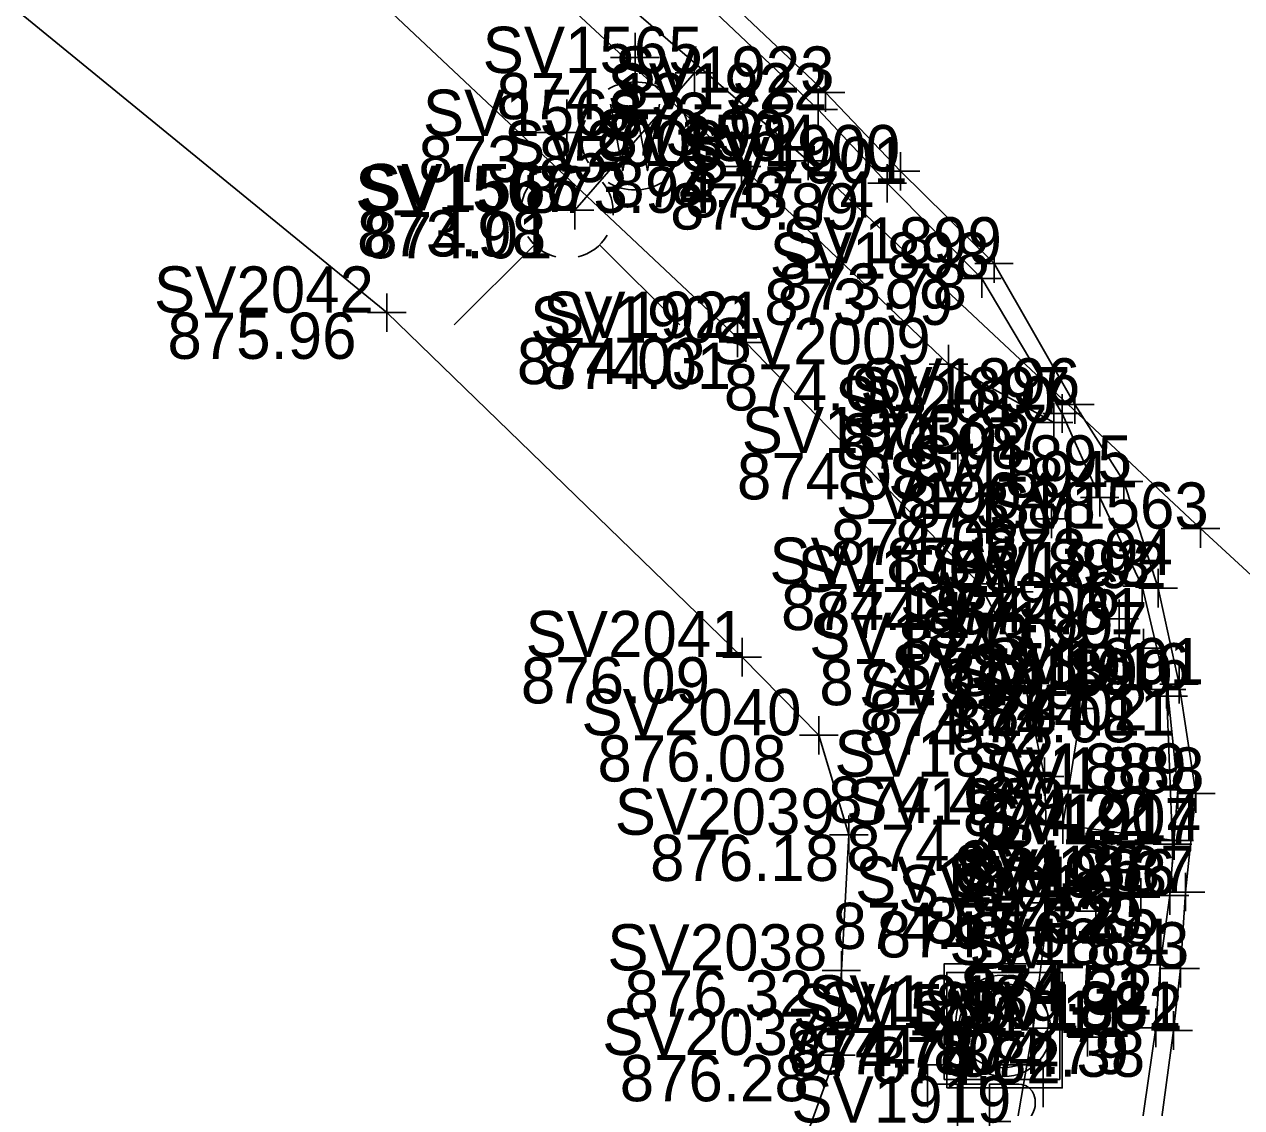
# Model space of a CAD drawing. Extents: x 1480001 to 1480402, y 379235 to 379603.
# Drawn here: x 1480114.39 to 1480145.99, y 379405.99 to 379434.1 of the extents above; entities that cross this region are included whole.
import ezdxf

# ---------------------------------------------------------------- set-up
doc = ezdxf.new("R2010")
doc.units = 0
for name, color, linetype in [('PV_X_Curb', 7, 'Continuous'), ('PV_X_Walk', 7, 'Continuous'), ('RD_X_Concrete_Pad', 7, 'Continuous'), ('SG_X_Poles', 7, 'Continuous'), ('SG_X_PullBox', 7, 'Continuous'), ('SV_X_Break_Lines', 7, 'Continuous'), ('SV_X_Shot_Marker', 7, 'Continuous'), ('SV_X_Text_Elevation', 7, 'Continuous'), ('SV_X_Text_Name', 7, 'Continuous'), ('UT_X_Water', 7, 'Continuous'), ('UT_X_Water_Cells', 7, 'Continuous')]:
    doc.layers.add(name, color=color, linetype=linetype)

msp = doc.modelspace()

# ---------------------------------------------------------------- linework, layer by layer
at = {"layer": 'PV_X_Curb'}
for points in [[(1480097.272, 379349.731), (1480114.906, 379368.678), (1480120.582, 379374.885), (1480122.682, 379377.153), (1480124.005, 379378.548), (1480138.475, 379394.29), (1480139.717, 379395.951), (1480141.648, 379398.861), (1480143.063, 379403.22), (1480143.762, 379408.065), (1480143.873, 379409.698), (1480144.124, 379411.499), (1480144.338, 379414.245), (1480144.085, 379416.674), (1480143.405, 379419.529), (1480142.307, 379421.83), (1480141.33, 379424.009), (1480139.247, 379427.506), (1480136.787, 379429.98), (1480135, 379431.897), (1480118.039, 379447.914)], [(1480097.622, 379349.287), (1480115.163, 379368.135), (1480120.989, 379374.507), (1480122.913, 379376.573), (1480123.248, 379376.579), (1480124.233, 379378.045), (1480138.666, 379393.676), (1480140.342, 379395.44), (1480142.173, 379398.797), (1480143.522, 379402.786), (1480144.219, 379407.995), (1480144.4, 379409.609), (1480144.536, 379411.589), (1480144.804, 379414.142), (1480144.365, 379416.981), (1480143.824, 379419.476), (1480142.93, 379422.24), (1480141.664, 379424.24), (1480139.564, 379427.9), (1480137.133, 379430.292), (1480135.19, 379432.332), (1480118.45, 379448.16)]]:
    msp.add_lwpolyline(points, dxfattribs=at)
at = {"layer": 'PV_X_Walk'}
for points in [[(1480106.316, 379456.227), (1480120.51, 379442.034), (1480133.01, 379430.413), (1480138.38, 379425.286), (1480141.112, 379423.774)], [(1480035.484, 379289.224), (1480050.568, 379305.437), (1480062.335, 379317.896), (1480064.038, 379319.719), (1480070.805, 379327.066), (1480078.054, 379334.946), (1480079.953, 379336.866), (1480094.208, 379352.393), (1480112.048, 379371.575), (1480117.348, 379377.211), (1480119.911, 379379.906), (1480121.511, 379381.77), (1480134.604, 379395.58), (1480136.695, 379398.148), (1480138.778, 379401.149), (1480140.004, 379404.725), (1480140.577, 379408.06), (1480140.982, 379411.311), (1480140.871, 379414.584), (1480140.225, 379417.636), (1480139.184, 379419.586), (1480133.124, 379425.845), (1480132.903, 379425.968), (1480114.834, 379442.96)]]:
    msp.add_lwpolyline(points, dxfattribs=at)
at = {"layer": 'RD_X_Concrete_Pad'}
msp.add_lwpolyline([(1480144.243, 379412.927), (1480141.349, 379413.336), (1480141.909, 379416.834), (1480144.038, 379416.848), (1480144.194, 379412.83)], dxfattribs=at)
at = {"layer": 'SG_X_Poles'}
for points in [[(1480138.271, 379406.729), (1480141.271, 379406.729), (1480141.271, 379409.729), (1480138.271, 379409.729)], [(1480138.334, 379406.505), (1480141.334, 379406.505), (1480141.334, 379409.505), (1480138.334, 379409.505)]]:
    msp.add_lwpolyline(points, close=True, dxfattribs=at)
for centre in [(1480139.771, 379408.229), (1480139.834, 379408.005)]:
    msp.add_circle(centre, 1.2, dxfattribs=at)
at = {"layer": 'SG_X_PullBox'}
for points in [[(1480138.937, 379407.108), (1480137.837, 379407.108), (1480137.837, 379406.008)], [(1480140.837, 379406.008), (1480140.837, 379407.108), (1480139.737, 379407.108)], [(1480137.981, 379406.608), (1480139.225, 379406.608)], [(1480138.611, 379406.608), (1480138.611, 379404.608)], [(1480139.449, 379404.608), (1480139.449, 379406.608), (1480140.205, 379406.608), (1480140.283, 379406.592), (1480140.394, 379406.56), (1480140.441, 379406.529), (1480140.488, 379406.497), (1480140.551, 379406.419), (1480140.598, 379406.34), (1480140.63, 379406.214), (1480140.63, 379406.025), (1480140.614, 379405.962), (1480140.583, 379405.868), (1480140.52, 379405.757), (1480140.457, 379405.71), (1480140.409, 379405.679), (1480140.378, 379405.663), (1480140.331, 379405.647), (1480140.189, 379405.631), (1480139.449, 379405.631)]]:
    msp.add_lwpolyline(points, dxfattribs=at)
at = {"layer": 'SV_X_Break_Lines'}
msp.add_lwpolyline([(1480127.721, 379395.358), (1480131.799, 379398.039), (1480133.273, 379401.352), (1480135.459, 379407.36), (1480135.6, 379409.555), (1480135.793, 379413.076), (1480135.014, 379415.657), (1480133.026, 379417.684), (1480123.803, 379426.624), (1480113.121, 379435.343), (1480106.984, 379440.926), (1480103.73, 379443.918), (1480102.529, 379445.074), (1480100.774, 379445.951), (1480096.595, 379444.059), (1480092.174, 379441.029), (1480086.377, 379436.591)], dxfattribs=at)
at = {"layer": 'SV_X_Shot_Marker'}
for p, q in [((1480131.786, 379433.343), (1480131.786, 379432.343)), ((1480131.286, 379432.843), (1480132.286, 379432.843)), ((1480131.786, 379432.843), (1480131.786, 379432.843)), ((1480135.19, 379432.832), (1480135.19, 379431.832)), ((1480134.69, 379432.332), (1480135.69, 379432.332)), ((1480135, 379432.397), (1480135, 379431.397)), ((1480135.19, 379432.332), (1480135.19, 379432.332)), ((1480134.5, 379431.897), (1480135.5, 379431.897)), ((1480135, 379431.897), (1480135, 379431.897)), ((1480133.01, 379430.913), (1480133.01, 379429.913)), ((1480134.739, 379431.059), (1480134.739, 379430.059)), ((1480134.239, 379430.559), (1480135.239, 379430.559)), ((1480134.739, 379430.559), (1480134.739, 379430.559)), ((1480137.133, 379430.792), (1480137.133, 379429.792)), ((1480132.51, 379430.413), (1480133.51, 379430.413)), ((1480133.01, 379430.413), (1480133.01, 379430.413)), ((1480136.633, 379430.292), (1480137.633, 379430.292)), ((1480136.787, 379430.48), (1480136.787, 379429.48)), ((1480137.133, 379430.292), (1480137.133, 379430.292)), ((1480136.287, 379429.98), (1480137.287, 379429.98)), ((1480136.787, 379429.98), (1480136.787, 379429.98)), ((1480128.679, 379429.782), (1480128.679, 379428.782)), ((1480128.179, 379429.282), (1480129.179, 379429.282)), ((1480128.679, 379429.282), (1480128.679, 379429.282)), ((1480139.564, 379428.4), (1480139.564, 379427.4)), ((1480139.247, 379428.006), (1480139.247, 379427.006)), ((1480139.064, 379427.9), (1480140.064, 379427.9)), ((1480139.564, 379427.9), (1480139.564, 379427.9)), ((1480138.747, 379427.506), (1480139.747, 379427.506)), ((1480139.247, 379427.506), (1480139.247, 379427.506)), ((1480123.803, 379427.124), (1480123.803, 379426.124)), ((1480123.303, 379426.624), (1480124.303, 379426.624)), ((1480123.803, 379426.624), (1480123.803, 379426.624)), ((1480132.903, 379426.468), (1480132.903, 379425.468)), ((1480133.124, 379426.345), (1480133.124, 379425.345)), ((1480132.403, 379425.968), (1480133.403, 379425.968)), ((1480132.624, 379425.845), (1480133.624, 379425.845)), ((1480132.903, 379425.968), (1480132.903, 379425.968)), ((1480133.124, 379425.845), (1480133.124, 379425.845)), ((1480138.38, 379425.786), (1480138.38, 379424.786)), ((1480137.88, 379425.286), (1480138.88, 379425.286)), ((1480138.38, 379425.286), (1480138.38, 379425.286)), ((1480141.33, 379424.509), (1480141.33, 379423.509)), ((1480141.664, 379424.74), (1480141.664, 379423.74)), ((1480141.112, 379424.274), (1480141.112, 379423.274)), ((1480141.164, 379424.24), (1480142.164, 379424.24)), ((1480141.664, 379424.24), (1480141.664, 379424.24)), ((1480140.83, 379424.009), (1480141.83, 379424.009)), ((1480141.33, 379424.009), (1480141.33, 379424.009)), ((1480140.612, 379423.774), (1480141.612, 379423.774)), ((1480141.112, 379423.774), (1480141.112, 379423.774)), ((1480138.625, 379423.478), (1480138.625, 379422.478)), ((1480138.125, 379422.978), (1480139.125, 379422.978)), ((1480138.625, 379422.978), (1480138.625, 379422.978)), ((1480142.93, 379422.74), (1480142.93, 379421.74)), ((1480142.307, 379422.33), (1480142.307, 379421.33)), ((1480142.43, 379422.24), (1480143.43, 379422.24)), ((1480142.93, 379422.24), (1480142.93, 379422.24)), ((1480141.058, 379421.773), (1480141.058, 379420.773)), ((1480141.807, 379421.83), (1480142.807, 379421.83)), ((1480142.307, 379421.83), (1480142.307, 379421.83)), ((1480144.924, 379421.519), (1480144.924, 379420.519)), ((1480140.558, 379421.273), (1480141.558, 379421.273)), ((1480141.058, 379421.273), (1480141.058, 379421.273)), ((1480144.424, 379421.019), (1480145.424, 379421.019)), ((1480144.924, 379421.019), (1480144.924, 379421.019)), ((1480139.184, 379420.086), (1480139.184, 379419.086)), ((1480140.079, 379419.878), (1480140.079, 379418.878)), ((1480143.405, 379420.029), (1480143.405, 379419.029)), ((1480143.824, 379419.976), (1480143.824, 379418.976)), ((1480138.684, 379419.586), (1480139.684, 379419.586)), ((1480139.184, 379419.586), (1480139.184, 379419.586)), ((1480142.905, 379419.529), (1480143.905, 379419.529)), ((1480143.324, 379419.476), (1480144.324, 379419.476)), ((1480143.405, 379419.529), (1480143.405, 379419.529)), ((1480143.824, 379419.476), (1480143.824, 379419.476)), ((1480139.579, 379419.378), (1480140.579, 379419.378)), ((1480140.079, 379419.378), (1480140.079, 379419.378)), ((1480142.812, 379419.182), (1480142.812, 379418.182)), ((1480142.312, 379418.682), (1480143.312, 379418.682)), ((1480142.812, 379418.682), (1480142.812, 379418.682)), ((1480143.444, 379418.417), (1480143.444, 379417.417)), ((1480133.026, 379418.184), (1480133.026, 379417.184)), ((1480140.225, 379418.136), (1480140.225, 379417.136)), ((1480142.944, 379417.917), (1480143.944, 379417.917)), ((1480143.444, 379417.917), (1480143.444, 379417.917)), ((1480132.526, 379417.684), (1480133.526, 379417.684)), ((1480133.026, 379417.684), (1480133.026, 379417.684)), ((1480139.725, 379417.636), (1480140.725, 379417.636)), ((1480140.225, 379417.636), (1480140.225, 379417.636)), ((1480141.909, 379417.334), (1480141.909, 379416.334)), ((1480144.038, 379417.348), (1480144.038, 379416.348)), ((1480144.365, 379417.481), (1480144.365, 379416.481)), ((1480143.865, 379416.981), (1480144.865, 379416.981)), ((1480144.085, 379417.174), (1480144.085, 379416.174)), ((1480144.365, 379416.981), (1480144.365, 379416.981)), ((1480141.409, 379416.834), (1480142.409, 379416.834)), ((1480141.679, 379416.851), (1480141.679, 379415.851)), ((1480141.909, 379416.834), (1480141.909, 379416.834)), ((1480143.538, 379416.848), (1480144.538, 379416.848)), ((1480143.585, 379416.674), (1480144.585, 379416.674)), ((1480144.038, 379416.848), (1480144.038, 379416.848)), ((1480144.085, 379416.674), (1480144.085, 379416.674)), ((1480141.179, 379416.351), (1480142.179, 379416.351)), ((1480141.679, 379416.351), (1480141.679, 379416.351)), ((1480135.014, 379416.157), (1480135.014, 379415.157)), ((1480134.514, 379415.657), (1480135.514, 379415.657)), ((1480135.014, 379415.657), (1480135.014, 379415.657)), ((1480140.871, 379415.084), (1480140.871, 379414.084)), ((1480144.338, 379414.745), (1480144.338, 379413.745)), ((1480140.371, 379414.584), (1480141.371, 379414.584)), ((1480140.871, 379414.584), (1480140.871, 379414.584)), ((1480144.804, 379414.642), (1480144.804, 379413.642)), ((1480143.838, 379414.245), (1480144.838, 379414.245)), ((1480144.304, 379414.142), (1480145.304, 379414.142)), ((1480144.338, 379414.245), (1480144.338, 379414.245)), ((1480144.804, 379414.142), (1480144.804, 379414.142)), ((1480141.349, 379413.836), (1480141.349, 379412.836)), ((1480135.793, 379413.576), (1480135.793, 379412.576)), ((1480140.849, 379413.336), (1480141.849, 379413.336)), ((1480141.349, 379413.336), (1480141.349, 379413.336)), ((1480144.194, 379413.33), (1480144.194, 379412.33)), ((1480144.243, 379413.427), (1480144.243, 379412.427)), ((1480135.293, 379413.076), (1480136.293, 379413.076)), ((1480135.793, 379413.076), (1480135.793, 379413.076)), ((1480143.694, 379412.83), (1480144.694, 379412.83)), ((1480143.743, 379412.927), (1480144.743, 379412.927)), ((1480144.194, 379412.83), (1480144.194, 379412.83)), ((1480144.243, 379412.927), (1480144.243, 379412.927)), ((1480143.37, 379411.952), (1480143.37, 379410.952)), ((1480144.124, 379411.999), (1480144.124, 379410.999)), ((1480144.536, 379412.089), (1480144.536, 379411.089)), ((1480140.982, 379411.811), (1480140.982, 379410.811)), ((1480142.207, 379411.592), (1480142.207, 379410.592)), ((1480144.036, 379411.589), (1480145.036, 379411.589)), ((1480144.536, 379411.589), (1480144.536, 379411.589)), ((1480140.482, 379411.311), (1480141.482, 379411.311)), ((1480140.982, 379411.311), (1480140.982, 379411.311)), ((1480142.87, 379411.452), (1480143.87, 379411.452)), ((1480143.37, 379411.452), (1480143.37, 379411.452)), ((1480143.624, 379411.499), (1480144.624, 379411.499)), ((1480144.124, 379411.499), (1480144.124, 379411.499)), ((1480141.707, 379411.092), (1480142.707, 379411.092)), ((1480142.207, 379411.092), (1480142.207, 379411.092)), ((1480135.6, 379410.055), (1480135.6, 379409.055)), ((1480143.873, 379410.198), (1480143.873, 379409.198)), ((1480144.4, 379410.109), (1480144.4, 379409.109)), ((1480143.373, 379409.698), (1480144.373, 379409.698)), ((1480143.873, 379409.698), (1480143.873, 379409.698)), ((1480135.1, 379409.555), (1480136.1, 379409.555)), ((1480135.6, 379409.555), (1480135.6, 379409.555)), ((1480143.9, 379409.609), (1480144.9, 379409.609)), ((1480144.4, 379409.609), (1480144.4, 379409.609)), ((1480140.577, 379408.56), (1480140.577, 379407.56)), ((1480143.762, 379408.565), (1480143.762, 379407.565)), ((1480144.219, 379408.495), (1480144.219, 379407.495)), ((1480141.99, 379408.326), (1480141.99, 379407.326)), ((1480135.459, 379407.86), (1480135.459, 379406.86)), ((1480140.077, 379408.06), (1480141.077, 379408.06)), ((1480140.577, 379408.06), (1480140.577, 379408.06)), ((1480141.49, 379407.826), (1480142.49, 379407.826)), ((1480141.99, 379407.826), (1480141.99, 379407.826)), ((1480143.262, 379408.065), (1480144.262, 379408.065)), ((1480143.719, 379407.995), (1480144.719, 379407.995)), ((1480143.762, 379408.065), (1480143.762, 379408.065)), ((1480144.219, 379407.995), (1480144.219, 379407.995)), ((1480134.959, 379407.36), (1480135.959, 379407.36)), ((1480135.459, 379407.36), (1480135.459, 379407.36))]:
    msp.add_line(p, q, dxfattribs=at)
at = {"layer": 'UT_X_Water'}
msp.add_line((1480131.786, 379432.843), (1480128.679, 379429.282), dxfattribs=at)
msp.add_lwpolyline([(1480225.088, 379345.601), (1480208.322, 379361.342), (1480207.346, 379362.25), (1480199.528, 379369.768), (1480193.21, 379375.651), (1480182.823, 379385.139), (1480177.927, 379389.525), (1480169.423, 379398.321), (1480161.035, 379406.189), (1480144.924, 379421.019), (1480134.739, 379430.559), (1480121.485, 379441.998), (1480113.085, 379450.369), (1480106.418, 379456.915), (1480094.539, 379467.985), (1480089.15, 379472.551), (1480086.751, 379474.713), (1480073.459, 379487.337), (1480068.123, 379493.187), (1480050.678, 379510.207), (1480044.404, 379515.873)], dxfattribs=at)
at = {"layer": 'UT_X_Water_Cells'}
for p, q in [((1480130.245, 379432.61), (1480130.245, 379433.881)), ((1480130.88, 379433.246), (1480129.608, 379433.246)), ((1480128.478, 379430.438), (1480128.478, 379432.158)), ((1480129.678, 379431.298), (1480127.278, 379431.298)), ((1480130.245, 379431.21), (1480130.245, 379431.21)), ((1480128.48, 379429.234), (1480128.48, 379429.234)), ((1480128.48, 379429.234), (1480128.48, 379429.234)), ((1480127.633, 379428.386), (1480125.553, 379426.308)), ((1480129.325, 379428.386), (1480131.405, 379426.308))]:
    msp.add_line(p, q, dxfattribs=at)
msp.add_lwpolyline([(1480129.608, 379432.03), (1480129.927, 379430.306), (1480130.245, 379432.03), (1480130.565, 379430.306), (1480130.882, 379432.03)], dxfattribs=at)
for centre, radius, start, end in [((1480130.245, 379431.211), 1.4, 60.0184, 120.0157), ((1480130.245, 379431.211), 1.4, 150.0184, 209.9816), ((1480130.245, 379431.211), 1.4, 330.0184, 29.9816), ((1480128.48, 379429.234), 1.2, 68.1395, 112.038), ((1480128.48, 379429.234), 1.2, 140.021, 184.0629), ((1480128.48, 379429.234), 1.2, 356.0165, 39.9889), ((1480130.245, 379431.211), 1.4, 239.9843, 299.9816), ((1480128.48, 379429.234), 1.2, 283.8239, 329.9097), ((1480128.48, 379429.234), 1.2, 211.8788, 255.8479)]:
    msp.add_arc(centre, radius, start, end, dxfattribs=at)

# ---------------------------------------------------------------- texts
at = {"layer": 'SV_X_Text_Elevation'}
for s, p in [('874.13', (1480126.647, 379431.643)), ('873.68', (1480129.54, 379431.132)), ('873.90', (1480129.255, 379430.697)), ('873.85', (1480124.623, 379430.01)), ('874.17', (1480129.6, 379429.359)), ('873.94', (1480127.379, 379429.213)), ('873.74', (1480131.54, 379429.092)), ('873.89', (1480131.156, 379428.78)), ('873.98', (1480123.029, 379428.082)), ('874.01', (1480123.188, 379428.034)), ('873.78', (1480133.952, 379426.7)), ('873.99', (1480133.597, 379426.306)), ('875.96', (1480118.106, 379425.424)), ('874.03', (1480127.178, 379424.768)), ('874.01', (1480127.832, 379424.645)), ('874.00', (1480132.551, 379424.086)), ('873.87', (1480136.042, 379423.04)), ('874.02', (1480135.614, 379422.809)), ('873.98', (1480135.462, 379422.574)), ('874.08', (1480132.89, 379421.778)), ('873.88', (1480137.299, 379421.04)), ('874.01', (1480137.015, 379420.63)), ('874.08', (1480135.323, 379420.073)), ('873.94', (1480139.293, 379419.819)), ('874.19', (1480134.035, 379418.386)), ('874.03', (1480137.68, 379418.329)), ('874.01', (1480138.532, 379418.276)), ('874.17', (1480134.94, 379418.178)), ('874.08', (1480137.077, 379417.482)), ('874.10', (1480138.201, 379416.717)), ('876.09', (1480127.281, 379416.484)), ('874.31', (1480135.028, 379416.436)), ('874.02', (1480138.649, 379415.781)), ('874.28', (1480136.306, 379415.634)), ('874.08', (1480138.35, 379415.474)), ('874.11', (1480139.333, 379415.648)), ('874.32', (1480136.057, 379415.151)), ('876.08', (1480129.269, 379414.457)), ('874.42', (1480135.259, 379413.384)), ('874.22', (1480138.754, 379413.045)), ('874.20', (1480139.107, 379412.942)), ('874.43', (1480135.728, 379412.136)), ('876.18', (1480130.635, 379411.876)), ('874.26', (1480138.525, 379411.63)), ('874.27', (1480138.65, 379411.727)), ('874.25', (1480138.943, 379410.389)), ('874.55', (1480135.37, 379410.111)), ('874.32', (1480137.748, 379410.252)), ('874.29', (1480138.521, 379410.299)), ('874.56', (1480136.519, 379409.892)), ('874.51', (1480138.695, 379408.498)), ('876.32', (1480129.969, 379408.355)), ('874.32', (1480138.778, 379408.409)), ('874.78', (1480134.168, 379407.029)), ('874.80', (1480134.861, 379406.86)), ('874.79', (1480138.159, 379406.865)), ('874.75', (1480134.241, 379406.805)), ('874.82', (1480136.387, 379406.626)), ('874.38', (1480138.578, 379406.795)), ('876.28', (1480129.847, 379406.16))]:
    msp.add_text(s, height=1.2, dxfattribs=at).set_placement(p)
at = {"layer": 'SV_X_Text_Name'}
for s, p in [('SV1565', (1480126.288, 379432.843)), ('SV1923', (1480129.711, 379432.332)), ('SV1922', (1480129.53, 379431.897)), ('SV1568', (1480124.737, 379431.21)), ('SV1564', (1480129.25, 379430.559)), ('SV2008', (1480126.84, 379430.413)), ('SV1900', (1480131.417, 379430.292)), ('SV1901', (1480131.609, 379429.98)), ('SV1567', (1480122.982, 379429.234)), ('SV1566', (1480123.105, 379429.282)), ('SV1899', (1480134.056, 379427.9)), ('SV1898', (1480133.739, 379427.506)), ('SV2042', (1480117.756, 379426.624)), ('SV1902', (1480127.522, 379425.845)), ('SV1921', (1480127.858, 379425.968)), ('SV2009', (1480132.21, 379425.286)), ('SV1896', (1480136.09, 379424.24)), ('SV1897', (1480135.832, 379424.009)), ('SV2010', (1480135.434, 379423.774)), ('SV1903', (1480133.013, 379422.978)), ('SV1895', (1480137.432, 379422.24)), ('SV1894', (1480136.818, 379421.83)), ('SV1904', (1480135.456, 379421.273)), ('SV1563', (1480139.426, 379421.019)), ('SV1874', (1480133.733, 379419.586)), ('SV1893', (1480137.907, 379419.529)), ('SV1905', (1480134.467, 379419.378)), ('SV1892', (1480138.335, 379419.476)), ('SV1906', (1480137.125, 379418.682)), ('SV1907', (1480137.832, 379417.917)), ('SV2041', (1480127.404, 379417.684)), ('SV1873', (1480134.765, 379417.636)), ('SV1891', (1480139.301, 379416.981)), ('SV1915', (1480136.884, 379416.834)), ('SV1890', (1480138.483, 379416.674)), ('SV1916', (1480138.937, 379416.848)), ('SV1908', (1480136.058, 379416.351)), ('SV2040', (1480128.854, 379415.657)), ('SV1872', (1480135.42, 379414.584)), ('SV1889', (1480138.849, 379414.245)), ('SV1888', (1480139.315, 379414.142)), ('SV1909', (1480135.728, 379413.336)), ('SV2039', (1480129.718, 379413.076)), ('SV1914', (1480139.227, 379412.927)), ('SV1917', (1480139.169, 379412.83)), ('SV1871', (1480135.955, 379411.311)), ('SV1913', (1480138.345, 379411.452)), ('SV1886', (1480138.569, 379411.499)), ('SV1887', (1480139.057, 379411.589)), ('SV1910', (1480137.078, 379411.092)), ('SV2038', (1480129.525, 379409.555)), ('SV1884', (1480138.403, 379409.698)), ('SV1883', (1480138.921, 379409.609)), ('SV1918', (1480134.736, 379408.229)), ('SV1589', (1480134.345, 379408.005)), ('SV1870', (1480135.013, 379408.06)), ('SV1911', (1480137.399, 379407.826)), ('SV1881', (1480138.717, 379408.065)), ('SV1882', (1480138.749, 379407.995)), ('SV2037', (1480129.393, 379407.36)), ('SV1919', (1480134.302, 379405.608))]:
    msp.add_text(s, height=1.2, dxfattribs=at).set_placement(p)

doc.saveas('drawing.dxf')
